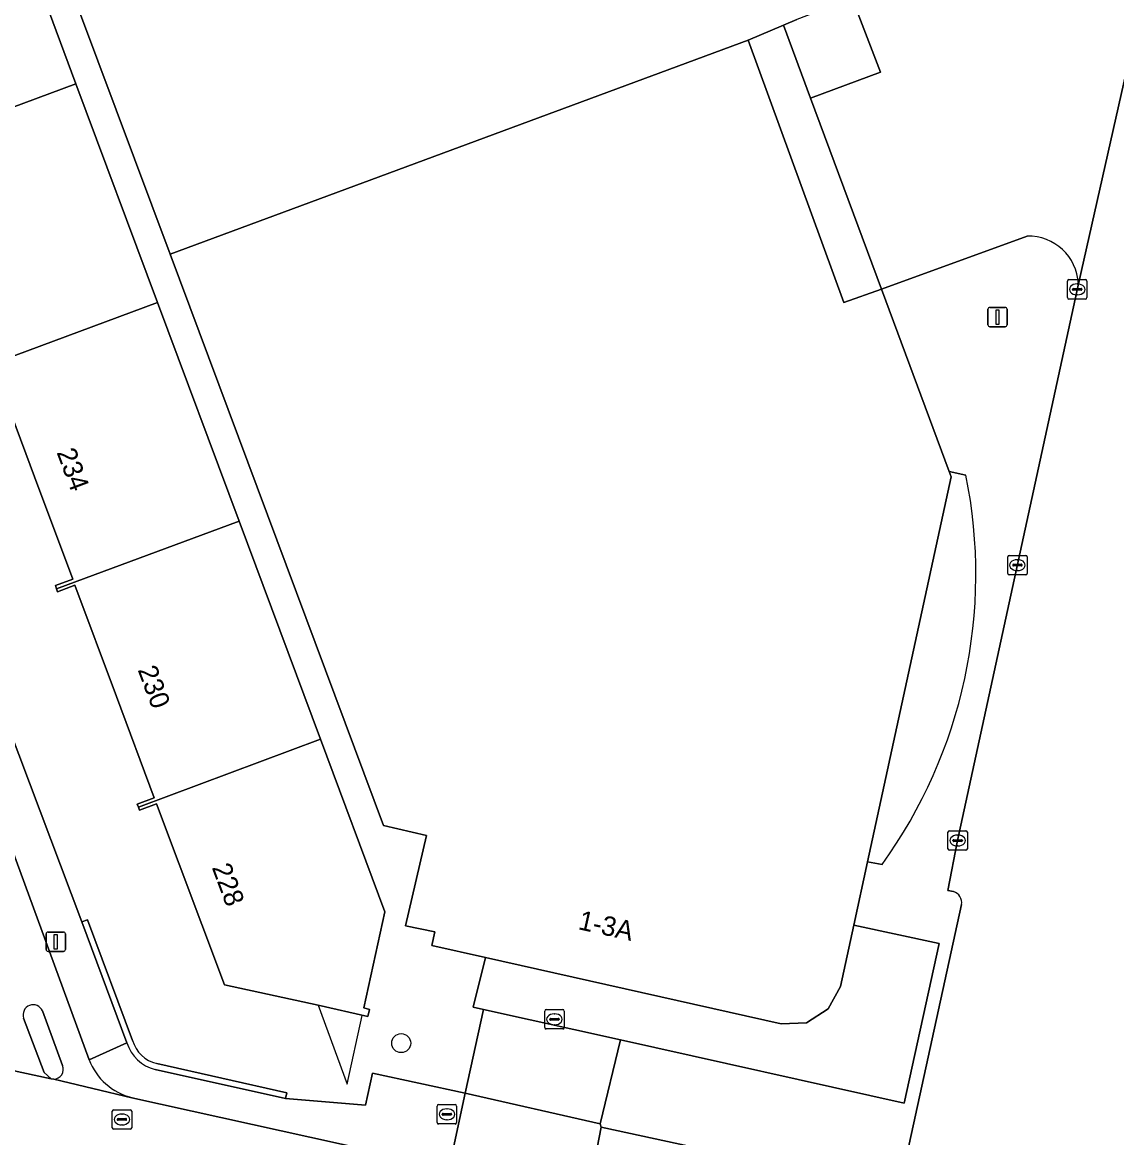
# Model space of a CAD drawing. Extents: x 162172 to 163187, y 382874 to 383685.
# Drawn here: x 162391 to 162447.3, y 383057.8 to 383115.2 of the extents above; entities that cross this region are included whole.
import ezdxf

# ---------------------------------------------------------------- set-up
doc = ezdxf.new("R2010")
doc.units = 0
for name, color, linetype in [('IMGEO_Boom', 7, 'Continuous'), ('IMGEO_Brandkraan', 7, 'Continuous'), ('IMGEO_Erf', 7, 'Continuous'), ('IMGEO_Fietspad_open', 7, 'Continuous'), ('IMGEO_Kolk', 7, 'Continuous'), ('IMGEO_Lichtmast', 7, 'Continuous'), ('IMGEO_Muur', 7, 'Continuous'), ('IMGEO_Pand', 7, 'Continuous'), ('IMGEO_Pand_nummerreeks', 7, 'Continuous'), ('IMGEO_Pand_overbouw', 7, 'Continuous'), ('IMGEO_Parkeervlak_open', 7, 'Continuous'), ('IMGEO_Rijbaan_lokaal_open', 7, 'Continuous'), ('IMGEO_Rioolput', 7, 'Continuous'), ('IMGEO_Verkeerseiland_open', 7, 'Continuous'), ('IMGEO_Voetpad_open', 7, 'Continuous')]:
    doc.layers.add(name, color=color, linetype=linetype)

msp = doc.modelspace()

# ---------------------------------------------------------------- linework, layer by layer
at = {"layer": 'IMGEO_Boom'}
msp.add_circle((162410.454, 383062.639), 0.489, dxfattribs=at)
at = {"layer": 'IMGEO_Brandkraan'}
for p, q in [((162412.308, 383058.552), (162412.308, 383059.404)), ((162412.383, 383059.478), (162413.235, 383059.478)), ((162412.796, 383059.258), (162412.821, 383059.258)), ((162413.309, 383059.404), (162413.309, 383058.552)), ((162412.567, 383058.972), (162412.567, 383058.984)), ((162413.005, 383058.935), (162412.607, 383058.935)), ((162412.61, 383059.021), (162413.008, 383059.021)), ((162412.819, 383058.698), (162412.794, 383058.698)), ((162413.051, 383058.984), (162413.051, 383058.972)), ((162413.235, 383058.478), (162412.383, 383058.478))]:
    msp.add_line(p, q, dxfattribs=at)
for points in [[(162412.308, 383058.552), (162412.308, 383059.404)], [(162412.383, 383059.478), (162413.235, 383059.478)], [(162413.309, 383059.404), (162413.309, 383058.552)], [(162413.235, 383058.478), (162412.383, 383058.478)]]:
    msp.add_lwpolyline(points, dxfattribs=at)
for centre, radius, start, end in [((162412.385, 383059.402), 0.0765, 91.55205, 178.44795), ((162412.385, 383059.402), 0.0765, 91.55205, 178.44795), ((162413.233, 383059.402), 0.0765, 1.55205, 88.44795), ((162413.233, 383059.402), 0.0765, 1.55205, 88.44795), ((162412.607, 383058.981), 0.0403, 85.87752, 175.75265), ((162412.604, 383058.971), 0.0366, 178.93798, 274.71019), ((162413.008, 383058.978), 0.043, 264.86636, 352.45326), ((162413.012, 383058.983), 0.0386, 1.73085, 96.63898), ((162412.385, 383058.554), 0.0765, 181.55205, 268.44795), ((162412.385, 383058.554), 0.0765, 181.55205, 268.44795), ((162413.233, 383058.554), 0.0765, 271.55205, 358.44795), ((162413.233, 383058.554), 0.0765, 271.55205, 358.44795)]:
    msp.add_arc(centre, radius, start, end, dxfattribs=at)
for centre, major_axis, ratio, start_param, end_param in [((162412.795, 383058.978), (-0.387, 0.002), 0.722429, 4.712389, 7.853982), ((162412.82, 383058.978), (-0.39, 0.002), 0.717154, 1.570796, 4.712389)]:
    msp.add_ellipse(centre, major_axis=major_axis, ratio=ratio, start_param=start_param, end_param=end_param, dxfattribs=at)
at = {"layer": 'IMGEO_Erf'}
for points in [[(162351.468, 383182.584), (162358.858, 383162.93), (162388.064, 383084.639), (162394.027, 383068.875), (162394.311, 383068.989), (162396.634, 383062.777)], [(162397.882, 383061.595), (162404.565, 383060.086), (162404.504, 383059.784), (162408.62, 383059.445), (162408.973, 383061.102), (162413.755, 383060.066), (162414.69, 383064.37), (162414.165, 383064.487), (162414.788, 383067.044), (162412.033, 383067.661), (162412.18, 383068.364), (162410.679, 383068.677), (162411.755, 383073.321), (162409.551, 383073.841), (162398.566, 383103.245), (162393.012, 383118.114), (162386.314, 383136.041)], [(162389.521, 383123.265), (162393.719, 383112.013), (162397.917, 383100.761), (162402.115, 383089.508), (162406.303, 383078.283), (162409.619, 383069.394), (162408.535, 383064.448), (162408.825, 383064.372), (162408.744, 383064.011), (162406.181, 383064.588), (162401.36, 383065.647), (162397.871, 383074.962), (162396.987, 383074.631), (162396.931, 383074.787), (162396.875, 383074.943), (162397.745, 383075.269), (162395.801, 383080.477), (162393.664, 383086.2), (162392.777, 383085.868), (162392.725, 383086.013), (162392.664, 383086.186), (162393.551, 383086.518), (162391.588, 383091.776), (162389.467, 383097.455)]]:
    msp.add_lwpolyline(points, dxfattribs=at)
msp.add_arc((162398.255, 383063.239), 1.686, 195.90207, 257.20953, dxfattribs=at)
at = {"layer": 'IMGEO_Fietspad_open'}
for points in [[(162394.394, 383061.785), (162384.643, 383088.38), (162380.978, 383087.017), (162389.922, 383062.817)], [(162389.018, 383061.534), (162392.445, 383060.806), (162392.086, 383061.133), (162391.027, 383063.924)], [(162391.998, 383064.296), (162393.03, 383061.483)], [(162392.58, 383060.778), (162396.598, 383059.833)]]:
    msp.add_lwpolyline(points, dxfattribs=at)
for centre, radius, start, end in [((162391.518, 383064.094), 0.52, 22.80322, 199.12147), ((162392.553, 383061.291), 0.514, 272.97822, 21.92177), ((162397.377, 383062.933), 3.196, 201.04627, 255.89351)]:
    msp.add_arc(centre, radius, start, end, dxfattribs=at)
at = {"layer": 'IMGEO_Kolk'}
for p, q in [((162444.742, 383101.004), (162444.742, 383101.856)), ((162444.817, 383101.93), (162445.669, 383101.93)), ((162445.23, 383101.71), (162445.255, 383101.71)), ((162445.743, 383101.856), (162445.743, 383101.004)), ((162445.001, 383101.424), (162445.001, 383101.436)), ((162445.439, 383101.387), (162445.041, 383101.387)), ((162445.044, 383101.473), (162445.442, 383101.473)), ((162445.253, 383101.15), (162445.228, 383101.15)), ((162445.485, 383101.436), (162445.485, 383101.424)), ((162445.669, 383100.93), (162444.817, 383100.93)), ((162441.663, 383086.813), (162441.663, 383087.665)), ((162441.738, 383087.739), (162442.59, 383087.739)), ((162442.151, 383087.519), (162442.176, 383087.519)), ((162442.664, 383087.665), (162442.664, 383086.813)), ((162442.59, 383086.739), (162441.738, 383086.739)), ((162441.922, 383087.233), (162441.922, 383087.245)), ((162442.36, 383087.196), (162441.962, 383087.196)), ((162441.965, 383087.282), (162442.363, 383087.282)), ((162442.174, 383086.959), (162442.149, 383086.959)), ((162442.406, 383087.245), (162442.406, 383087.233)), ((162438.663, 383073.565), (162439.515, 383073.565)), ((162438.588, 383072.639), (162438.588, 383073.491)), ((162438.847, 383073.059), (162438.847, 383073.071)), ((162439.285, 383073.022), (162438.887, 383073.022)), ((162438.89, 383073.108), (162439.288, 383073.108)), ((162439.076, 383073.345), (162439.101, 383073.345)), ((162439.331, 383073.071), (162439.331, 383073.059)), ((162439.589, 383073.491), (162439.589, 383072.639)), ((162439.515, 383072.565), (162438.663, 383072.565)), ((162439.099, 383072.785), (162439.074, 383072.785)), ((162417.915, 383064.367), (162418.767, 383064.367)), ((162417.84, 383063.441), (162417.84, 383064.293)), ((162418.099, 383063.861), (162418.099, 383063.873)), ((162418.537, 383063.824), (162418.139, 383063.824)), ((162418.142, 383063.91), (162418.54, 383063.91)), ((162418.328, 383064.147), (162418.353, 383064.147)), ((162418.583, 383063.873), (162418.583, 383063.861)), ((162418.841, 383064.293), (162418.841, 383063.441)), ((162418.767, 383063.367), (162417.915, 383063.367)), ((162418.351, 383063.587), (162418.326, 383063.587))]:
    msp.add_line(p, q, dxfattribs=at)
for points in [[(162444.742, 383101.004), (162444.742, 383101.856)], [(162444.817, 383101.93), (162445.669, 383101.93)], [(162445.743, 383101.856), (162445.743, 383101.004)], [(162445.669, 383100.93), (162444.817, 383100.93)], [(162441.663, 383086.813), (162441.663, 383087.665)], [(162441.738, 383087.739), (162442.59, 383087.739)], [(162442.664, 383087.665), (162442.664, 383086.813)], [(162442.59, 383086.739), (162441.738, 383086.739)], [(162438.663, 383073.565), (162439.515, 383073.565)], [(162438.588, 383072.639), (162438.588, 383073.491)], [(162439.589, 383073.491), (162439.589, 383072.639)], [(162439.515, 383072.565), (162438.663, 383072.565)], [(162417.915, 383064.367), (162418.767, 383064.367)], [(162417.84, 383063.441), (162417.84, 383064.293)], [(162418.841, 383064.293), (162418.841, 383063.441)], [(162418.767, 383063.367), (162417.915, 383063.367)]]:
    msp.add_lwpolyline(points, dxfattribs=at)
for centre, radius, start, end in [((162444.819, 383101.854), 0.0765, 91.55205, 178.44795), ((162444.819, 383101.854), 0.0765, 91.55205, 178.44795), ((162445.667, 383101.854), 0.0765, 1.55205, 88.44795), ((162445.667, 383101.854), 0.0765, 1.55205, 88.44795), ((162445.041, 383101.433), 0.0403, 85.87752, 175.75265), ((162445.038, 383101.423), 0.0366, 178.93798, 274.71019), ((162445.442, 383101.43), 0.043, 264.86636, 352.45326), ((162445.446, 383101.435), 0.0386, 1.73085, 96.63898), ((162444.819, 383101.006), 0.0765, 181.55205, 268.44795), ((162444.819, 383101.006), 0.0765, 181.55205, 268.44795), ((162445.667, 383101.006), 0.0765, 271.55205, 358.44795), ((162445.667, 383101.006), 0.0765, 271.55205, 358.44795), ((162441.74, 383087.663), 0.0765, 91.55205, 178.44795), ((162441.74, 383087.663), 0.0765, 91.55205, 178.44795), ((162442.588, 383087.663), 0.0765, 1.55205, 88.44795), ((162442.588, 383087.663), 0.0765, 1.55205, 88.44795), ((162441.74, 383086.815), 0.0765, 181.55205, 268.44795), ((162441.74, 383086.815), 0.0765, 181.55205, 268.44795), ((162441.962, 383087.242), 0.0403, 85.87752, 175.75265), ((162441.959, 383087.232), 0.0366, 178.93798, 274.71019), ((162442.363, 383087.239), 0.043, 264.86636, 352.45326), ((162442.367, 383087.244), 0.0386, 1.73085, 96.63898), ((162442.588, 383086.815), 0.0765, 271.55205, 358.44795), ((162442.588, 383086.815), 0.0765, 271.55205, 358.44795), ((162438.665, 383073.489), 0.0765, 91.55205, 178.44795), ((162438.665, 383073.489), 0.0765, 91.55205, 178.44795), ((162439.513, 383073.489), 0.0765, 1.55205, 88.44795), ((162439.513, 383073.489), 0.0765, 1.55205, 88.44795), ((162438.887, 383073.068), 0.0403, 85.87752, 175.75265), ((162438.884, 383073.058), 0.0366, 178.93798, 274.71019), ((162439.288, 383073.065), 0.043, 264.86636, 352.45326), ((162439.292, 383073.07), 0.0386, 1.73085, 96.63898), ((162438.665, 383072.641), 0.0765, 181.55205, 268.44795), ((162438.665, 383072.641), 0.0765, 181.55205, 268.44795), ((162439.513, 383072.641), 0.0765, 271.55205, 358.44795), ((162439.513, 383072.641), 0.0765, 271.55205, 358.44795), ((162417.917, 383064.291), 0.0765, 91.55205, 178.44795), ((162417.917, 383064.291), 0.0765, 91.55205, 178.44795), ((162418.765, 383064.291), 0.0765, 1.55205, 88.44795), ((162418.765, 383064.291), 0.0765, 1.55205, 88.44795), ((162418.139, 383063.87), 0.0403, 85.87752, 175.75265), ((162418.136, 383063.86), 0.0366, 178.93798, 274.71019), ((162418.54, 383063.867), 0.043, 264.86636, 352.45326), ((162418.544, 383063.872), 0.0386, 1.73085, 96.63898), ((162417.917, 383063.443), 0.0765, 181.55205, 268.44795), ((162417.917, 383063.443), 0.0765, 181.55205, 268.44795), ((162418.765, 383063.443), 0.0765, 271.55205, 358.44795), ((162418.765, 383063.443), 0.0765, 271.55205, 358.44795)]:
    msp.add_arc(centre, radius, start, end, dxfattribs=at)
for centre, major_axis, ratio, start_param, end_param in [((162445.229, 383101.43), (-0.387, 0.002), 0.722429, 4.712389, 7.853982), ((162445.254, 383101.43), (-0.39, 0.002), 0.717154, 1.570796, 4.712389), ((162442.15, 383087.239), (-0.387, 0.002), 0.722429, 4.712389, 7.853982), ((162442.175, 383087.239), (-0.39, 0.002), 0.717154, 1.570796, 4.712389), ((162439.075, 383073.065), (-0.387, 0.002), 0.722429, 4.712389, 7.853982), ((162439.1, 383073.065), (-0.39, 0.002), 0.717154, 1.570796, 4.712389), ((162418.327, 383063.867), (-0.387, 0.002), 0.722429, 4.712389, 7.853982), ((162418.352, 383063.867), (-0.39, 0.002), 0.717154, 1.570796, 4.712389)]:
    msp.add_ellipse(centre, major_axis=major_axis, ratio=ratio, start_param=start_param, end_param=end_param, dxfattribs=at)
at = {"layer": 'IMGEO_Lichtmast'}
for p, q in [((162440.745, 383100.504), (162441.535, 383100.504)), ((162441.535, 383100.504), (162440.745, 383100.504)), ((162440.645, 383099.604), (162440.645, 383100.404)), ((162440.645, 383100.404), (162440.645, 383099.604)), ((162441.635, 383100.404), (162441.635, 383099.604)), ((162441.635, 383099.604), (162441.635, 383100.404)), ((162441.535, 383099.504), (162440.745, 383099.504)), ((162440.745, 383099.504), (162441.535, 383099.504)), ((162392.184, 383067.458), (162392.184, 383068.258)), ((162392.184, 383068.258), (162392.184, 383067.458)), ((162392.284, 383068.358), (162393.074, 383068.358)), ((162393.074, 383068.358), (162392.284, 383068.358)), ((162393.174, 383068.258), (162393.174, 383067.458)), ((162393.174, 383067.458), (162393.174, 383068.258)), ((162393.074, 383067.358), (162392.284, 383067.358)), ((162392.284, 383067.358), (162393.074, 383067.358))]:
    msp.add_line(p, q, dxfattribs=at)
for points in [[(162441.065, 383100.379), (162441.215, 383100.379), (162441.215, 383099.629), (162441.065, 383099.629), (162441.065, 383100.379)], [(162392.604, 383068.233), (162392.754, 383068.233), (162392.754, 383067.483), (162392.604, 383067.483), (162392.604, 383068.233)]]:
    msp.add_lwpolyline(points, dxfattribs=at)
for centre, start, end in [((162440.745, 383100.404), 90, 180), ((162440.745, 383100.404), 90, 180), ((162441.535, 383100.404), 0, 90), ((162441.535, 383100.404), 360, 90), ((162440.745, 383099.604), 180, 270), ((162440.745, 383099.604), 180, 270), ((162441.535, 383099.604), 270, 0), ((162441.535, 383099.604), 270, 0), ((162392.284, 383068.258), 90, 180), ((162392.284, 383068.258), 90, 180), ((162393.074, 383068.258), 0, 90), ((162393.074, 383068.258), 360, 90), ((162392.284, 383067.458), 180, 270), ((162392.284, 383067.458), 180, 270), ((162393.074, 383067.458), 270, 0), ((162393.074, 383067.458), 270, 0)]:
    msp.add_arc(centre, 0.1, start, end, dxfattribs=at)
at = {"layer": 'IMGEO_Muur'}
for points in [[(162396.634, 383062.777), (162394.311, 383068.989), (162394.027, 383068.875), (162396.342, 383062.654)], [(162397.792, 383061.287), (162404.504, 383059.784), (162404.565, 383060.086), (162397.882, 383061.595)]]:
    msp.add_lwpolyline(points, dxfattribs=at)
for centre, radius, start, end in [((162398.262, 383063.238), 2.006, 196.9096, 256.46575), ((162398.255, 383063.239), 1.686, 195.90207, 257.20953)]:
    msp.add_arc(centre, radius, start, end, dxfattribs=at)
at = {"layer": 'IMGEO_Pand'}
msp.add_lwpolyline([(162426.675, 383130.669), (162393.012, 383118.114), (162398.566, 383103.245), (162428.312, 383114.263), (162430.126, 383115.031), (162430.805, 383115.318)], dxfattribs=at)
for points in [[(162380.124, 383119.767), (162380.189, 383119.597), (162381.067, 383119.933), (162383.181, 383114.263), (162385.14, 383109.009), (162384.259, 383108.693), (162384.329, 383108.518), (162393.719, 383112.013), (162389.521, 383123.265)], [(162428.312, 383114.263), (162398.566, 383103.245), (162409.551, 383073.841), (162411.755, 383073.321), (162410.679, 383068.677), (162412.18, 383068.364), (162412.033, 383067.661), (162414.788, 383067.044), (162429.999, 383063.636), (162431.314, 383063.684), (162432.431, 383064.409), (162433.054, 383065.554), (162433.739, 383068.707), (162434.449, 383071.975), (162438.754, 383091.786), (162438.655, 383092.052), (162435.169, 383101.446), (162433.233, 383100.756)], [(162397.917, 383100.761), (162393.719, 383112.013), (162384.329, 383108.518), (162384.39, 383108.363), (162385.245, 383108.703), (162387.369, 383103.042), (162389.348, 383097.767), (162388.464, 383097.437), (162388.531, 383097.267)], [(162397.917, 383100.761), (162388.531, 383097.267), (162388.591, 383097.113), (162389.467, 383097.455), (162391.588, 383091.776), (162393.551, 383086.518), (162392.664, 383086.186), (162392.725, 383086.013), (162402.115, 383089.508)], [(162402.115, 383089.508), (162392.725, 383086.013), (162392.777, 383085.868), (162393.664, 383086.2), (162395.801, 383080.477), (162397.745, 383075.269), (162396.875, 383074.943), (162396.931, 383074.787), (162406.303, 383078.283)], [(162406.303, 383078.283), (162396.931, 383074.787), (162396.987, 383074.631), (162397.871, 383074.962), (162401.36, 383065.647), (162406.181, 383064.588), (162408.744, 383064.011), (162408.825, 383064.372), (162408.535, 383064.448), (162409.619, 383069.394)]]:
    msp.add_lwpolyline(points, close=True, dxfattribs=at)
at = {"layer": 'IMGEO_Pand_overbouw'}
for points in [[(162428.312, 383114.263), (162433.233, 383100.756), (162435.169, 383101.446), (162430.126, 383115.031)], [(162438.136, 383067.771), (162433.739, 383068.707), (162433.054, 383065.554), (162432.431, 383064.409), (162431.314, 383063.684), (162429.999, 383063.636), (162414.788, 383067.044), (162414.165, 383064.487), (162414.69, 383064.37), (162421.74, 383062.801), (162436.343, 383059.549)], [(162408.451, 383064.069), (162406.181, 383064.588), (162407.675, 383060.527)]]:
    msp.add_lwpolyline(points, close=True, dxfattribs=at)
msp.add_lwpolyline([(162439.511, 383091.872), (162438.655, 383092.052), (162438.754, 383091.786), (162434.449, 383071.975), (162435.198, 383071.827)], dxfattribs=at)
msp.add_arc((162414.47, 383086.774), 25.555, 324.20571, 11.50836, dxfattribs=at)
at = {"layer": 'IMGEO_Parkeervlak_open'}
msp.add_lwpolyline([(162420.694, 383058.49), (162421.74, 383062.801), (162414.69, 383064.37), (162413.755, 383060.066)], close=True, dxfattribs=at)
at = {"layer": 'IMGEO_Rijbaan_lokaal_open'}
for points in [[(162464.576, 383187.403), (162462.513, 383177.732), (162460.495, 383168.899), (162458.243, 383158.824), (162456.293, 383150.279), (162454.075, 383140.44), (162452.054, 383131.655), (162445.304, 383101.713), (162439.089, 383073.065), (162438.579, 383070.494), (162438.868, 383070.439)], [(162445.304, 383101.713), (162452.054, 383131.655), (162450.97, 383131.164), (162441.72, 383127.729), (162438.2, 383137.127), (162449.72, 383141.441), (162451.074, 383141.982)], [(162437.147, 383117.761), (162433.654, 383116.416), (162435.119, 383112.615), (162431.52, 383111.275), (162435.169, 383101.446), (162442.66, 383104.175)], [(162411.956, 383056.427), (162396.598, 383059.833), (162392.58, 383060.778), (162392.445, 383060.806), (162389.018, 383061.534), (162267.92, 383088.659), (162234.912, 383095.955), (162234.142, 383092.59), (162256.343, 383087.743), (162265.344, 383085.659), (162267.262, 383085.257), (162369.028, 383062.601), (162385.606, 383058.831), (162387.741, 383058.335), (162387.584, 383057.578), (162396.928, 383055.458), (162397.132, 383056.208), (162398.331, 383055.984), (162434.465, 383047.898), (162434.341, 383047.118), (162442.682, 383045.253), (162442.859, 383046.021), (162536.233, 383025.143)], [(162439.287, 383069.766), (162436.061, 383054.999), (162446.46, 383052.742), (162447.272, 383056.614)], [(162420.537, 383057.245), (162420.746, 383058.322), (162420.694, 383058.49), (162413.755, 383060.066), (162413.141, 383057.26)]]:
    msp.add_lwpolyline(points, dxfattribs=at)
msp.add_lwpolyline([(162433.654, 383116.416), (162430.805, 383115.318), (162430.126, 383115.031), (162431.52, 383111.275), (162435.119, 383112.615)], close=True, dxfattribs=at)
for centre, radius, start, end in [((162442.713, 383101.582), 2.594, 2.90546, 91.17735), ((162438.716, 383069.878), 0.581, 348.91981, 74.89178)]:
    msp.add_arc(centre, radius, start, end, dxfattribs=at)
at = {"layer": 'IMGEO_Rioolput'}
for p, q in [((162395.661, 383059.212), (162396.513, 383059.212)), ((162395.586, 383058.286), (162395.586, 383059.138)), ((162395.845, 383058.706), (162395.845, 383058.718)), ((162396.283, 383058.669), (162395.885, 383058.669)), ((162395.888, 383058.755), (162396.286, 383058.755)), ((162396.074, 383058.992), (162396.099, 383058.992)), ((162396.329, 383058.718), (162396.329, 383058.706)), ((162396.587, 383059.138), (162396.587, 383058.286)), ((162396.513, 383058.212), (162395.661, 383058.212)), ((162396.097, 383058.432), (162396.072, 383058.432))]:
    msp.add_line(p, q, dxfattribs=at)
for points in [[(162395.661, 383059.212), (162396.513, 383059.212)], [(162395.586, 383058.286), (162395.586, 383059.138)], [(162396.587, 383059.138), (162396.587, 383058.286)], [(162396.513, 383058.212), (162395.661, 383058.212)]]:
    msp.add_lwpolyline(points, dxfattribs=at)
for centre, radius, start, end in [((162395.663, 383059.136), 0.0765, 91.55205, 178.44795), ((162395.663, 383059.136), 0.0765, 91.55205, 178.44795), ((162396.511, 383059.136), 0.0765, 1.55205, 88.44795), ((162396.511, 383059.136), 0.0765, 1.55205, 88.44795), ((162395.885, 383058.715), 0.0403, 85.87752, 175.75265), ((162395.882, 383058.705), 0.0366, 178.93798, 274.71019), ((162396.286, 383058.712), 0.043, 264.86636, 352.45326), ((162396.29, 383058.717), 0.0386, 1.73085, 96.63898), ((162395.663, 383058.288), 0.0765, 181.55205, 268.44795), ((162395.663, 383058.288), 0.0765, 181.55205, 268.44795), ((162396.511, 383058.288), 0.0765, 271.55205, 358.44795), ((162396.511, 383058.288), 0.0765, 271.55205, 358.44795)]:
    msp.add_arc(centre, radius, start, end, dxfattribs=at)
for centre, major_axis, ratio, start_param, end_param in [((162396.073, 383058.712), (-0.387, 0.002), 0.722429, 4.712389, 7.853982), ((162396.098, 383058.712), (-0.39, 0.002), 0.717154, 1.570796, 4.712389)]:
    msp.add_ellipse(centre, major_axis=major_axis, ratio=ratio, start_param=start_param, end_param=end_param, dxfattribs=at)
at = {"layer": 'IMGEO_Verkeerseiland_open'}
for points in [[(162391.027, 383063.924), (162392.086, 383061.133), (162392.445, 383060.806), (162392.58, 383060.778)], [(162393.03, 383061.483), (162391.998, 383064.296)]]:
    msp.add_lwpolyline(points, dxfattribs=at)
for centre, radius, start, end in [((162391.518, 383064.094), 0.52, 22.80322, 199.12147), ((162392.553, 383061.291), 0.514, 272.97822, 21.92177)]:
    msp.add_arc(centre, radius, start, end, dxfattribs=at)
at = {"layer": 'IMGEO_Voetpad_open'}
for points in [[(162349.929, 383181.214), (162355.514, 383166.364), (162360.998, 383151.695), (162366.758, 383136.336), (162375.617, 383112.518), (162382.099, 383095.223), (162383.86, 383090.523), (162384.643, 383088.38), (162394.394, 383061.785), (162396.342, 383062.654), (162394.027, 383068.875), (162388.064, 383084.639), (162358.858, 383162.93)], [(162442.66, 383104.175), (162435.169, 383101.446), (162438.655, 383092.052), (162439.511, 383091.872)], [(162438.868, 383070.439), (162438.579, 383070.494), (162439.089, 383073.065), (162445.304, 383101.713)], [(162439.511, 383091.872), (162438.655, 383092.052), (162438.754, 383091.786), (162434.449, 383071.975), (162435.198, 383071.827)], [(162435.198, 383071.827), (162434.449, 383071.975), (162433.739, 383068.707), (162438.136, 383067.771), (162436.343, 383059.549), (162421.74, 383062.801), (162420.694, 383058.49), (162420.746, 383058.322), (162436.061, 383054.999), (162439.287, 383069.766)], [(162396.342, 383062.654), (162394.394, 383061.785)], [(162413.755, 383060.066), (162408.973, 383061.102), (162408.62, 383059.445), (162404.504, 383059.784), (162397.792, 383061.287)], [(162396.598, 383059.833), (162411.956, 383056.427)], [(162413.141, 383057.26), (162413.755, 383060.066)], [(162435.78, 383053.781), (162436.061, 383054.999), (162420.746, 383058.322), (162420.537, 383057.245)]]:
    msp.add_lwpolyline(points, dxfattribs=at)
for points in [[(162431.52, 383111.275), (162430.126, 383115.031), (162428.312, 383114.263), (162433.233, 383100.756), (162435.169, 383101.446)], [(162421.74, 383062.801), (162436.343, 383059.549), (162438.136, 383067.771), (162433.739, 383068.707), (162433.054, 383065.554), (162432.431, 383064.409), (162431.314, 383063.684), (162429.999, 383063.636), (162414.788, 383067.044), (162414.165, 383064.487), (162414.69, 383064.37)]]:
    msp.add_lwpolyline(points, close=True, dxfattribs=at)
for centre, radius, start, end in [((162442.713, 383101.582), 2.594, 2.90546, 91.17735), ((162414.47, 383086.774), 25.555, 324.20571, 11.50836), ((162414.47, 383086.774), 25.555, 324.20571, 11.50836), ((162438.716, 383069.878), 0.581, 348.91981, 74.89178), ((162398.262, 383063.238), 2.006, 196.9096, 256.46575), ((162397.377, 383062.933), 3.196, 201.04627, 255.89351)]:
    msp.add_arc(centre, radius, start, end, dxfattribs=at)

# ---------------------------------------------------------------- texts
at = {"layer": 'IMGEO_Pand_nummerreeks'}
for s, rotation, p in [('234', 290.47157, (162392.714, 383093.047)), ('230', 290.47157, (162396.887, 383081.855)), ('228', 290.5346, (162400.701, 383071.681)), ('1-3A', 347.52489, (162419.52, 383068.509))]:
    msp.add_text(s, height=1, rotation=rotation, dxfattribs=at).set_placement(p)

doc.saveas('drawing.dxf')
